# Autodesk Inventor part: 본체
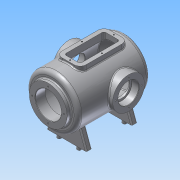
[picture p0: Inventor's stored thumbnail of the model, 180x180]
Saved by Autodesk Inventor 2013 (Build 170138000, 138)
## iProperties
Created: 2016-02
Part Number: 본체
Material: 알루미늄 6061
Document SubType Name: Modeling
Designer: mduedu
Density: 2.71 g/cm^3
Mass: 2843.89 g
Surface Area: 2031.16 cm^2
Volume: 1049.41 cm^3
Author: mduedu
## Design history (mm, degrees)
sketch "스케치2"
  geometry: L1 (0, 100)-(0, -100); L2 (65, -75.993)-(65, 100); L3 (65, 100)-(0, 100); A1 r 100 centre (0, 0) between (0, -100) and (65, -75.993); 2 further points
  constraints: 6 end point, 2 midpoint, 2 point on circle, 1 centre point, 1 coincident, 1 horizontal, 1 parallel, 1 vertical
  dimensions: "d3" = 200 distance of L1.start L1.end; "d5" = 130 diameter of L2 L1; "d6" = 100 radius of A1
revolve "회전1" sketch "스케치2" stored, may be unused: angle "d7" = 90 deg
sketch "스케치3"
  geometry: C1 r 47.5 at (0, 0); 1 further point
  constraints: 1 centre point, 1 coincident
  dimensions: "d8" = 95 diameter of C1
extrude "돌출2" join sketch "스케치3" distance "d10" = 10; taper "d11" = 0 deg
sketch "스케치5"
  geometry: L1 (47.5, 110)-(47.5, 100) reference; L2 (47.5, 100)-(65, 100) reference; L3 (65, 100)-(65, -75.993) reference; L4 (-65, -75.993)-(-65, 100) reference; L5 (-65, 100)-(-47.5, 100) reference; L6 (-47.5, 100)-(-47.5, 110) reference; L7 (-47.5, 110)-(47.5, 110) reference; L8 (55, 85)-(55, -71.239); L9 (0, 85)-(55, 85); L10 (0, 85)-(0, -90); A1 r 100 centre (0, 0) between (0, -100) and (65, -75.993) reference; A2 r 100 centre (0, 0) between (-65, -75.993) and (0, -100) reference; A3 r 90 centre (0, 0) between (0, -90) and (55, -71.239); 1 further point
  constraints: 6 end point, 2 point on circle, 1 centre point, 1 parallel, 1 perpendicular, 1 point on line, 1 vertical
  dimensions: "d13" = 10 distance between parallel lines of L3 L8; "d14" = 10 radial gap between concentric circles of A3 A1; "d15" = 15 distance between parallel lines of L9 L2
revolve "회전2" sketch "스케치5" stored, may be unused: angle "d16" = 90 deg
hole "구멍1" diameter "d19" = 65; stored, may be unused: countersink angle "d23" = 90 deg, drill point angle "d25" = 118 deg; dims "d17" = 10, "d18" = 10, "d20" = 6, "d21" = 4, "d22" = 2, "d24" = 8
node "작업 평면1"
sketch "스케치6"
  geometry: L1 (47.5, 110)-(-47.5, 110) reference; C1 r 40 at (0, -17); 1 further point
  constraints: 1 centre point, 1 vertical alignment
  dimensions: "d27" = 80 diameter of C1; "d29" = 127 distance from line of C1.centre L1
extrude "돌출3" join sketch "스케치6" stored distance "d30" = 10; taper "d31" = 0 deg
hole "구멍2" diameter "d34" = 42; stored, may be unused: countersink angle "d38" = 90 deg, drill point angle "d40" = 118 deg; dims "d32" = 10, "d33" = 10, "d35" = 6, "d36" = 52, "d37" = 18, "d39" = 8
sketch "스케치7" dims "d41" = 65
  geometry: C1 r 40 at (0, 0) reference; 3 further points
  constraints: 2 vertical alignment, 1 coincident, 2 other
hole "구멍3" sketch "스케치7" at (0, 32.5) diameter "d43" = 3.242; stored, may be unused: countersink angle "d47" = 90 deg, drill point angle "d49" = 118 deg; dims "d44" = 11, "d45" = 13, "d46" = 18, "d48" = 13
sketch "스케치8" dims "d53" = 80
  geometry: 3 further points
  constraints: 2 vertical alignment, 1 coincident, 2 other
hole "구멍4" sketch "스케치8" at (0, 40) diameter "d56" = 3.242; stored, may be unused: countersink angle "d60" = 90 deg, drill point angle "d62" = 118 deg; dims "d57" = 11, "d58" = 13, "d59" = 18, "d61" = 13
fillet "모깎기1" dims "d66" = 10
fillet "모깎기2" dims "d67" = 3
fillet "모깎기3" dims "d68" = 0.3
chamfer "모따기1" distance "d69" = 1; stored, may be unused: second distance "d70" = 2, angle "d71" = 45 deg
node "작업 평면5"
sketch "스케치10"
  geometry: L1 (-50, -64)-(50, -64); L2 (50, -64)-(50, -50); L3 (50, -50)-(-50, -50); L4 (-50, -50)-(-50, -64); L5 (-50, 0)-(50, 0); L6 (-50, 64)-(50, 64); L7 (50, 64)-(50, 50); L8 (50, 50)-(-50, 50); L9 (-50, 50)-(-50, 64); 2 further points
  constraints: 18 end point, 4 symmetric about line, 2 parallel, 2 perpendicular, 1 coincident, 1 horizontal, 1 midpoint
  dimensions: "d80" = 14 distance of L3.end L1.start; "d82" = 100 distance of L1.start L1.end; "d130" = 50 horizontal distance of L3.end point (0, 0); "d131" = 50 horizontal distance of L3.end point (0, 0); "d132" = 100 distance of L5.start L5.end
extrude "돌출5" join sketch "스케치10" stored distance "d84" = 10; taper "d85" = 0 deg
feature "면 기울기3" dims angle "d135" = 20 deg
sketch "스케치11"
  geometry: L1 (-85, -50)-(-85, 50); L2 (-65, 90)-(-65, -71.239) reference; L3 (-100, -50)-(-41.533, -50) reference; L4 (-100, 50)-(-41.533, 50) reference; 1 further point
  constraints: 2 end point, 2 point on line
  dimensions: "d87" = 20 distance between parallel lines of L1 L2
feature "리브1" sketch "스케치11" dims "d88" = 1, "d89" = 8, "d90" = 0, "d91" = 0, "d92" = 1, "d93" = 1
fillet "모깎기5" dims "d103" = 3
fillet "모깎기6" dims "d105" = 3
node "작업 평면6"
sketch "스케치15"
  geometry: L1 (-30, 60)-(30, 60); L2 (30, 60)-(30, -60); L3 (30, -60)-(-30, -60); L4 (-30, -60)-(-30, 60); 2 further points
  constraints: 8 end point, 2 parallel, 1 horizontal, 1 midpoint, 1 perpendicular, 1 vertical alignment
  dimensions: "d110" = 60 distance of L2.end L3.end; "d112" = 60 distance from line of L3 point (0, 0); "d113" = 120 distance of L1.end L2.end
extrude "돌출8" join sketch "스케치15" stored distance "d114" = 10; taper "d115" = 0 deg
fillet "모깎기7" dims "d116" = 15
sketch "스케치16"
  geometry: L1 (-30, -45)-(-30, 45) reference; L2 (30, 45)-(30, -45) reference; L3 (-15, 60)-(15, 60) reference; L4 (15, -60)-(-15, -60) reference; L5 (-20, -45)-(-20, 45); L6 (-15, 50)-(15, 50); L7 (20, 45)-(20, -45); L8 (15, -50)-(-15, -50); A1 r 15 centre (-15, -45) between (-30, -45) and (-15, -60) reference; A2 r 15 centre (-15, 45) between (-15, 60) and (-30, 45) reference; A3 r 15 centre (15, 45) between (30, 45) and (15, 60) reference; A4 r 15 centre (15, -45) between (15, -60) and (30, -45) reference; A5 r 5 centre (-15, -45) between (-20, -45) and (-15, -50); A6 r 5 centre (-15, 45) between (-15, 50) and (-20, 45); A7 r 5 centre (15, 45) between (20, 45) and (15, 50); A8 r 5 centre (15, -45) between (15, -50) and (20, -45)
  constraints: 8 end point, 8 point on circle, 4 centre point, 7 other
  dimensions: "d137" = 10 distance between parallel lines of L5 L1
extrude "돌출9" cut sketch "스케치16" stored distance "d118" = 10; taper "d119" = 0 deg
fillet "모깎기8" dims "d120" = 3
sketch "스케치17"
  geometry: L1 (-30, -45)-(-30, 45) reference; L2 (30, 45)-(30, -45) reference; L3 (-20, 45)-(-20, -45) reference; L4 (-15, -50)-(15, -50) reference; L5 (20, -45)-(20, 45) reference; L6 (15, 50)-(-15, 50) reference; L7 (-15, 60)-(15, 60) reference; L8 (15, -60)-(-15, -60) reference; L9 (15, 55)-(-15, 55); L10 (-25, 45)-(-25, -45); L11 (-15, -55)-(15, -55); L12 (25, -45)-(25, 45); A1 r 5 centre (-15, 45) between (-15, 50) and (-20, 45) reference; A2 r 5 centre (-15, -45) between (-20, -45) and (-15, -50) reference; A3 r 5 centre (15, -45) between (15, -50) and (20, -45) reference; A4 r 5 centre (15, 45) between (20, 45) and (15, 50) reference; A5 r 15 centre (-15, 45) between (-15, 60) and (-30, 45) reference; A6 r 15 centre (15, 45) between (30, 45) and (15, 60) reference; A7 r 15 centre (15, -45) between (15, -60) and (30, -45) reference; A8 r 15 centre (-15, -45) between (-30, -45) and (-15, -60) reference; A9 r 10 centre (-15, 45) between (-15, 55) and (-25, 45); A10 r 10 centre (-15, -45) between (-25, -45) and (-15, -55); A11 r 10 centre (15, -45) between (15, -55) and (25, -45); A12 r 10 centre (15, 45) between (25, 45) and (15, 55); 4 further points
  constraints: 8 end point, 8 point on circle, 4 centre point, 4 midpoint, 7 other
  dimensions: "d138" = 5 distance between parallel lines of L9 L7
hole "구멍5" sketch "스케치17" at (0, 55), (25, 0), (0, -55), (-25, 0) diameter "d122" = 3.242; stored, may be unused: countersink angle "d126" = 90 deg, drill point angle "d128" = 118 deg; dims "d123" = 9, "d124" = 13, "d125" = 18, "d127" = 11
fillet "모깎기9" dims "d129" = 3
sketch "스케치18"
  geometry: L1 (-46.807, 50)-(46.807, 50) reference; L2 (50, 53)-(50, 61) reference; L3 (46.807, 64)-(-46.807, 64) reference; L4 (-50, 61)-(-50, 53) reference; L5 (-50, 57)-(50, 57); L6 (0, 64)-(0, 50); C1 r 5 at (-25, 57); C2 r 5 at (25, 57); 5 further points; 4 other entities
  constraints: 4 end point, 4 midpoint, 2 centre point, 1 point on line, 1 symmetric about line, 5 other
  dimensions: "d139" = 10 diameter of C1; "d141" = 25 distance from line of L6 C1.centre; "d147" = 57 vertical distance of C2.centre point (0, 0) (derived)
extrude "돌출10" join sketch "스케치18" distance "d142" = 10; taper "d143" = 0 deg
chamfer "모따기2" distance "d144" = 1; stored, may be unused: second distance "d145" = 2, angle "d146" = 45 deg
node "작업 평면7"
fillet "모깎기10" dims "d148" = 0.5
node "솔리드2"
pattern_circular "원형 패턴1" dims angle "d51" = 360 deg
mirror "대칭1"
pattern_circular "원형 패턴2" dims angle "d64" = 360 deg
mirror "대칭2"
node "투영된 루프1"
node "절단 모서리 투영1"
node "절단 모서리 투영2"
node "절단 모서리 투영3"
other parameters: "d26" = 75
